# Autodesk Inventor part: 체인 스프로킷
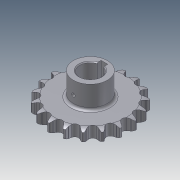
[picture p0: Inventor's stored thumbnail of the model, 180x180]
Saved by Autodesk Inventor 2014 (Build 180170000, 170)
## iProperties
Created: 2014-07
Part Number: 체인 스프로킷
Material: 강
Document SubType Name: Modeling
Designer: KYOUNG IL JANG
Density: 7.85 g/cm^3
Appearance: 강철
Mass: 738.603 g
Surface Area: 236.854 cm^2
Volume: 94.0896 cm^3
CustomPartVersion: 1
Company: 한국ATC센터
Author: KYOUNG IL JANG
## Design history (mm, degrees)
sketch "이론적 톱니 프로파일"
  geometry: L1 (0, 0)-(0, 45.567); L2 (0, 0)-(14.795, 43.098); L3 (0, 45.567)-(14.795, 43.098); L4 (0, 45.567)-(5.661, 50.015); L5 (5.661, 50.015)-(-5.141, 45.406); L6 (-12.428, 43.493)-(-5.573, 46.417); L7 (-5.141, 45.406)-(-5.573, 46.417); L8 (5.573, 46.417)-(5.141, 45.406); L9 (0, 0)-(8.138, 48.771); A1 r 45.567 centre (0, 0) between (0, 45.567) and (14.795, 43.098); A2 r 49.445 centre (0, 0) between (7.302, 48.903) and (-7.302, 48.903); A3 r 4.545 centre (0, 45.567) between (-3.574, 42.758) and (3.574, 42.758); A4 r 7.453 centre (12.428, 43.493) between (7.302, 48.903) and (5.573, 46.417); A5 r 7.453 centre (-12.428, 43.493) between (-5.573, 46.417) and (-7.302, 48.903); A6 r 11.745 centre (5.661, 50.015) between (-5.141, 45.406) and (-3.574, 42.758); A7 r 11.745 centre (-5.661, 50.015) between (3.574, 42.758) and (5.141, 45.406); 2 further points
  constraints: 18 end point, 15 point on circle, 7 centre point, 3 coincident, 3 point on line, 3 symmetric about line, 3 tangent, 1 equal radius, 1 midpoint, 1 parallel, 1 vertical, 1 other
  dimensions: "d0" = 91.13301 diameter of A1 (computed from da_p, da_z); "d2" = 18.9474 deg angle of L2 L1 (computed from da_z); "d3" = 4.545 radius of A3 (= 0.5 x da_Dr + da_SC); "d10" = 128.158 deg angle of L4 L1 (computed from da_z); "d11" = 15.0526 deg angle of L5 L4 (computed from da_z); "d12" = 7.2 distance of L3.start L4.end (= 0.8 x da_Dr); "d13" = 11.745 distance of L4.end L5.end (= 1.3 x da_Dr + da_SC); "d14" = 12.6 distance of A4.centre L1.end (= 1.4 x da_Dr); "d23" = 4.5 distance from line of L9.end L3 (= da_Ha)
sketch "톱니 프로파일"
  geometry: L1 (0, 0)-(0, 45.567); L2 (0, 45.567)-(4.203, 43.837); L3 (0, 45.567)-(-4.203, 43.837); A1 r 4.545 centre (0, 45.567) between (-4.203, 43.837) and (4.203, 43.837); A2 r 22.68 centre (25.176, 35.206) between (7.12, 48.93) and (4.203, 43.837); A3 r 22.68 centre (-25.176, 35.206) between (-4.203, 43.837) and (-7.12, 48.93); A4 r 49.445 centre (0, 0) between (-7.12, 48.93) and (7.12, 48.93) reference; 1 further point
  constraints: 9 point on circle, 6 end point, 3 centre point, 2 tangent, 1 coincident, 1 equal radius, 1 vertical, 1 other
  dimensions: "d44" = 135.263 deg angle of L3 L2 (= da_Alfa); "d45" = 22.68 radius of A2 (= da_Re); "d46" = 4.545 radius of A1 (= da_Ri)
sketch "단면 프로파일"
  geometry: L1 (49.445, 0)-(-49.445, 0) reference; L2 (33.265, 6.65)-(-33.265, 6.65); L3 (-33.265, 6.65)-(-33.265, -6.65); L4 (-33.265, -6.65)-(33.265, -6.65); L5 (33.265, -6.65)-(33.265, 6.65); L6 (33.265, 6.65)-(49.445, 6.65); L7 (49.445, 6.65)-(49.445, -6.65); L8 (49.445, -6.65)-(33.265, -6.65); L9 (33.265, -6.65)-(33.265, 6.65); L10 (42.183, 6.65)-(0, 6.65); L11 (0, 6.65)-(0, -6.65); L12 (0, -6.65)-(42.183, -6.65); L13 (0, 6.65)-(0, -6.65); L14 (49.445, 4.775)-(49.445, -4.775); A1 r 15 centre (42.183, -8.35) between (49.445, 4.775) and (42.183, 6.65); A2 r 15 centre (42.183, 8.35) between (42.183, -6.65) and (49.445, -4.775); 2 further points
  constraints: 26 end point, 7 midpoint, 5 perpendicular, 4 parallel, 4 point on circle, 3 point on line, 3 symmetric about line, 2 centre point, 2 horizontal, 2 tangent, 1 collinear, 1 other
  dimensions: "d30" = 13.3 distance between parallel lines of L8 L6 (= da_Bf); "d31" = 66.53007 distance between parallel lines of L3 L5 (= da_Ds); "d32" = 13.3 distance between parallel lines of L4 L2 (= da_Bs); "d33" = 1.875 distance from line of L14.start L6 (= da_Ba); "d34" = 15 radius of A1 (= da_Rx); "d43" = 6.65 distance between parallel lines of L4 L1 (computed from da_k, da_pt, da_Bs)
revolve "슈라우드" stored, may be unused: angle "d36" = 90 deg
revolve "스트랜드" stored, may be unused: angle "d37" = 90 deg
extrude "이론적 톱니" cut sketch "이론적 톱니 프로파일" stored distance "d18" = 10; taper "d19" = 0 deg; dims "d49" = 0, "form_type" = 0 [user parameter]
extrude "톱니" cut sketch "톱니 프로파일" stored distance "d47" = 10; taper "d48" = 0 deg; dims "d50" = 10, "form_type" = 0 [user parameter]
node "타이밍 평면"
node "작업 평면3"
sketch "스케치5"
  geometry: C1 r 20 at (0, -45.567); 1 further point
  constraints: 1 centre point, 1 coincident
  dimensions: "d52" = 40 diameter of C1
extrude "돌출4" join sketch "스케치5" stored distance "d53" = 10; taper "d54" = 0 deg
sketch "스케치6"
  geometry: L1 (4, 11.843)-(4, 16.5); L2 (4, 16.5)-(-4, 16.5); L3 (-4, 16.5)-(-4, 11.843); A1 r 12.5 centre (0, 0) between (4, 11.843) and (-4, 11.843); 1 further point
  constraints: 6 end point, 2 parallel, 2 point on circle, 1 centre point, 1 coincident, 1 perpendicular, 1 vertical
  dimensions: "d55" = 25 diameter of A1; "d56" = 29 dimension on A1 L2 (computed from d55); "d57" = 8 distance of L1.end L2.end
extrude "돌출5" cut sketch "스케치6" stored distance "d58" = 10; taper "d59" = 0 deg
fillet "모깎기2" dims "d60" = 3
chamfer "모따기1" distance "d61" = 1; stored, may be unused: second distance "d62" = 2, angle "d63" = 45 deg
node "작업 평면4"
sketch "스케치7"
  geometry: L1 (-13.5, -13.3)-(13.5, -13.3) reference; 4 further points
  constraints: 1 vertical alignment
  dimensions: "d65" = 25 distance from line of point (0, 11.7) L1
hole "구멍1" sketch "스케치7" at (0, 11.7) diameter "d66" = 4.134; stored, may be unused: countersink angle "d70" = 90 deg, drill point angle "d72" = 118 deg; dims "d67" = 6, "d68" = 4, "d69" = 2, "d71" = 8
body "Solid1"
pattern_linear "스트랜드 패턴" dims "d40" = 24 (= da_pt)
pattern_circular "톱니 패턴" dims angle "d21" = 360 deg
other parameters: "da_p" = 15 [user parameter; used in 1 equation term], "da_Dr" = 9 [user parameter; used in 4 equation terms], "da_SC" = 0.045 [user parameter; used in 2 equation terms], "da_Ha" = 4.5 [user parameter; used in 1 equation term], "da_pt" = 24 [user parameter; used in 2 equation terms], "da_Bf" = 13.3 [user parameter; used in 1 equation term], "d28" = 0, "d29" = 0, "da_Ba" = 1.875 [user parameter; used in 1 equation term], "da_Rx" = 15 [user parameter; used in 1 equation term], "da_Ra" = 0.6 [user parameter], "da_Bs" = 13.3 [user parameter; used in 2 equation terms], "da_Ds" = 66.53007 [user parameter; used in 1 equation term], "d42" = 0, "da_Re" = 22.68 [user parameter; used in 1 equation term], "da_Ri" = 4.545 [user parameter; used in 1 equation term], "da_Alfa" = 135.263 deg [user parameter; used in 1 equation term]
